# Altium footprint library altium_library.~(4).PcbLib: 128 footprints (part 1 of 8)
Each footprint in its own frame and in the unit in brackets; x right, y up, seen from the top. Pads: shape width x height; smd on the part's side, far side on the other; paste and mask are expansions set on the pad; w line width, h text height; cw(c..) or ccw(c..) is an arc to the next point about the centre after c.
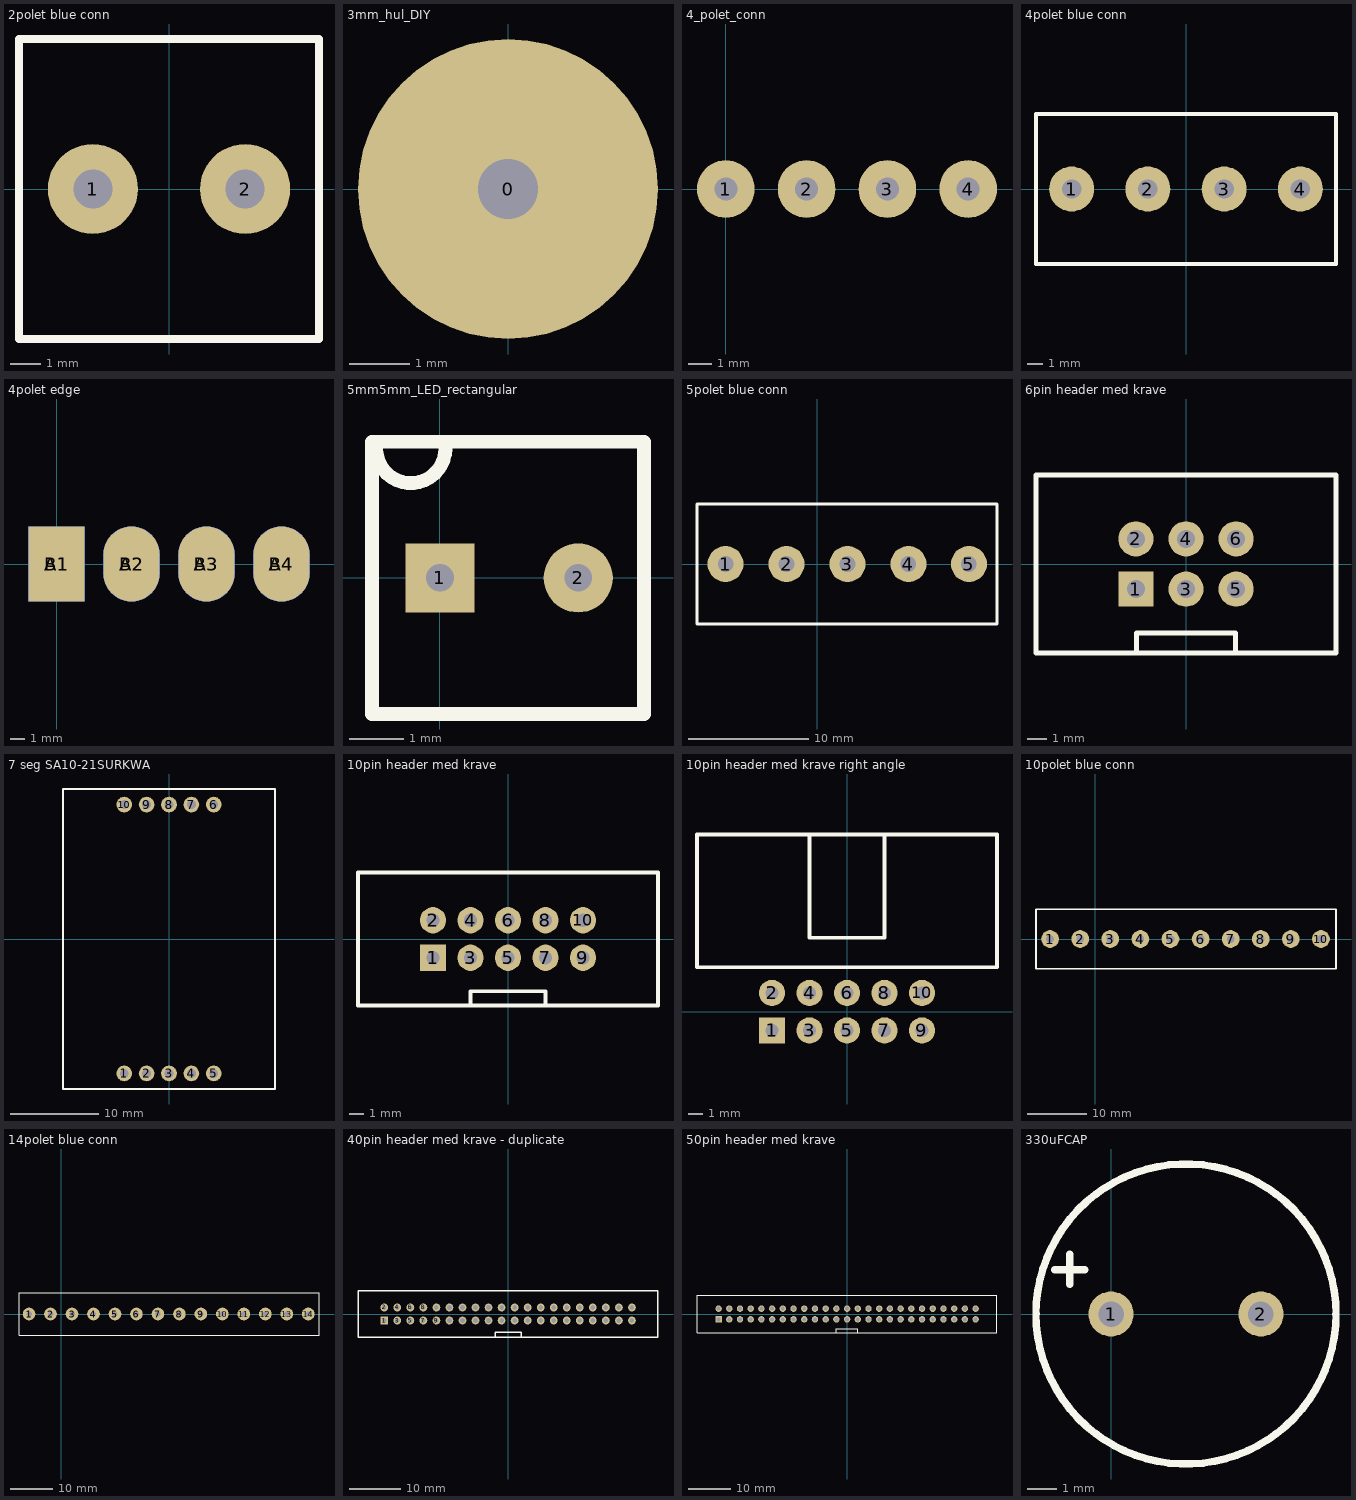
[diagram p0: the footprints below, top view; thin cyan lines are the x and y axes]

## 2polet blue conn [mm]
pads (2):
  round 3 hole 1.3: 1(-2.54,0) 2(2.54,0)
Top Overlay:
  lines w0.254: -5,-5 5,-5 5,5 -5,5 -5,-5

## 3mm_hul_DIY [mm]
pads (1):
  round 5 hole 1: 0(0,0)

## 4_polet_conn [mm]
pads (4):
  round 2.5 hole 1: 1(0,0) 2(3.5,0) 3(7,0) 4(10.5,0)

## 4polet blue conn [mm]
pads (4):
  round 3 hole 1.3: 1(-7.62,0) 2(-2.54,0) 3(2.54,0) 4(7.62,0)
Top Overlay:
  lines w0.254: -10,-5 10,-5 10,5 -10,5 -10,-5

## 4polet edge [mil]
pads (8):
  rect 150x200 smd: A1(0,0)
  oval 150x200 smd: A2(200,0) A3(400,0) A4(600,0)
  rect 150x200 smd far side: B1(0,0)
  oval 150x200 smd far side: B2(200,0) B3(400,0) B4(600,0)

## 5mm5mm_LED_rectangular [mil]
pads (2):
  rect 50x50 hole 20: 1(0,0)
  round 50 hole 20: 2(100,0)
Top Overlay:
  lines w10: -46.06,93.5 ccw(c-21.06,93.5) 3.94,93.5 ; 25,98.43 147.64,98.43 147.64,-98.43 -49.21,-98.43 -49.21,98.43 75,98.43

## 5polet blue conn [mm]
pads (5):
  round 3 hole 1.3: 1(-7.62,0) 2(-2.54,0) 3(2.54,0) 4(7.62,0) 5(12.66,0)
Top Overlay:
  lines w0.254: -10,-5 15,-5 15,5 -10,5 -10,-5

## 6pin header med krave [mil]
pads (6):
  rect 70x70 hole 35.43: 1(-100,-50)
  round 70 hole 35.43: 2(-100,50) 3(0,-50) 4(0,50) 5(100,-50) 6(100,50)
Top Overlay:
  lines w10: -98.43,-173.23 -98.43,-137.8 98.43,-137.8 98.43,-173.23 ; -299.21,-177.17 -299.21,177.17 299.21,177.17 299.21,-177.17 -299.21,-177.17

## 7 seg SA10-21SURKWA [mil] "7 segment display 25,4mm 260mcd"
pads (10):
  round 70 hole 39.37: 1(-200,-600) 2(-100,-600) 3(0,-600) 4(100,-600) 5(200,-600) 6(200,600) 7(100,600) 8(0,600) 9(-100,600) 10(-200,600)
Top Overlay:
  lines w10: -472.44,-669.29 472.44,-669.29 472.44,669.29 -472.44,669.29 -472.44,-669.29

## 10pin header med krave [mil]
pads (10):
  rect 70x70 hole 35.43: 1(-200,-50)
  round 70 hole 35.43: 2(-200,50) 3(-100,-50) 4(-100,50) 5(0,-50) 6(0,50) 7(100,-50) 8(100,50) 9(200,-50) 10(200,50)
Top Overlay:
  lines w10: -100,-175 -100,-139.57 100,-139.57 100,-175 ; -400,-177.17 -400,177.17 400,177.17 400,-177.17 -400,-177.17

## 10pin header med krave right angle [mil]
pads (10):
  rect 70x70 hole 35.43: 1(-200,-50)
  round 70 hole 35.43: 2(-200,50) 3(-100,-50) 4(-100,50) 5(0,-50) 6(0,50) 7(100,-50) 8(100,50) 9(200,-50) 10(200,50)
Top Overlay:
  lines w10: -100,472.44 -100,196.85 100,196.85 100,472.44 ; -400,118.11 -400,472.44 400,472.44 400,118.11 -400,118.11

## 10polet blue conn [mm]
pads (10):
  round 3 hole 1.3: 1(-7.62,0) 2(-2.54,0) 3(2.54,0) 4(7.62,0) 5(12.7,0) 6(17.78,0) 7(22.86,0) 8(27.94,0) 9(33.02,0) 10(38.1,0)
Top Overlay:
  lines w0.254: -10,-5 -10,5 40.64,5 40.64,-5 -10,-5

## 14polet blue conn [mm]
pads (14):
  round 3 hole 1.3: 1(-7.62,0) 2(-2.54,0) 3(2.54,0) 4(7.62,0) 5(12.7,0) 6(17.78,0) 7(22.86,0) 8(27.94,0) 9(33.02,0) 10(38.1,0) 11(43.18,0) 12(48.26,0) 13(53.34,0) 14(58.42,0)
Top Overlay:
  lines w0.254: -10,-5 60.96,-5 60.96,5 -10,5 -10,-5

## 40pin header med krave - duplicate [mil]
pads (40):
  rect 60x60 hole 35.43: 1(-950,-50)
  round 60 hole 35.43: 2(-950,50) 3(-850,-50) 4(-850,50) 5(-750,-50) 6(-750,50) 7(-650,-50) 8(-650,50) 9(-550,-50) 10(-550,50) 11(-450,-50) 12(-450,50) 13(-350,-50) 14(-350,50) 15(-250,-50) 16(-250,50) 17(-150,-50) 18(-150,50) 19(-50,-50) 20(-50,50) 21(50,-50) 22(50,50) 23(150,-50) 24(150,50) 25(250,-50) 26(250,50) 27(350,-50) 28(350,50) 29(450,-50) 30(450,50) 31(550,-50) 32(550,50) 33(650,-50) 34(650,50) 35(750,-50) 36(750,50) 37(850,-50) 38(850,50) 39(950,-50) 40(950,50)
Top Overlay:
  lines w10: -100,-175 -100,-139.57 100,-139.57 100,-175 ; -1151.57,-177.17 -1151.57,177.17 1150,177.17 1150,-177.17 -1151.57,-177.17

## 50pin header med krave [mil]
pads (50):
  rect 60x60 hole 35.43: 1(-1200,-50)
  round 60 hole 35.43: 2(-1200,50) 3(-1100,-50) 4(-1100,50) 5(-1000,-50) 6(-1000,50) 7(-900,-50) 8(-900,50) 9(-800,-50) 10(-800,50) 11(-700,-50) 12(-700,50) 13(-600,-50) 14(-600,50) 15(-500,-50) 16(-500,50) 17(-400,-50) 18(-400,50) 19(-300,-50) 20(-300,50) 21(-200,-50) 22(-200,50) 23(-100,-50) 24(-100,50) 25(0,-50) 26(0,50) 27(100,-50) 28(100,50) 29(200,-50) 30(200,50) 31(300,-50) 32(300,50) 33(400,-50) 34(400,50) 35(500,-50) 36(500,50) 37(600,-50) 38(600,50) 39(700,-50) 40(700,50) 41(800,-50) 42(800,50) 43(900,-50) 44(900,50) 45(1000,-50) 46(1000,50) 47(1100,-50) 48(1100,50) 49(1200,-50) 50(1200,50)
Top Overlay:
  lines w10: -100,-175 -100,-139.57 100,-139.57 100,-175 ; -1401.57,-177.17 -1401.57,177.17 1400,177.17 1400,-177.17 -1401.57,-177.17

## 330uFCAP [mil]
pads (2):
  round 60 hole 34: 1(0,0) 2(200,0)
Top Overlay:
  circle w10: c100,0 r200
  lines w10: -74.8,59.06 -34.8,59.06 ; -55.12,39.37 -55.12,79.37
